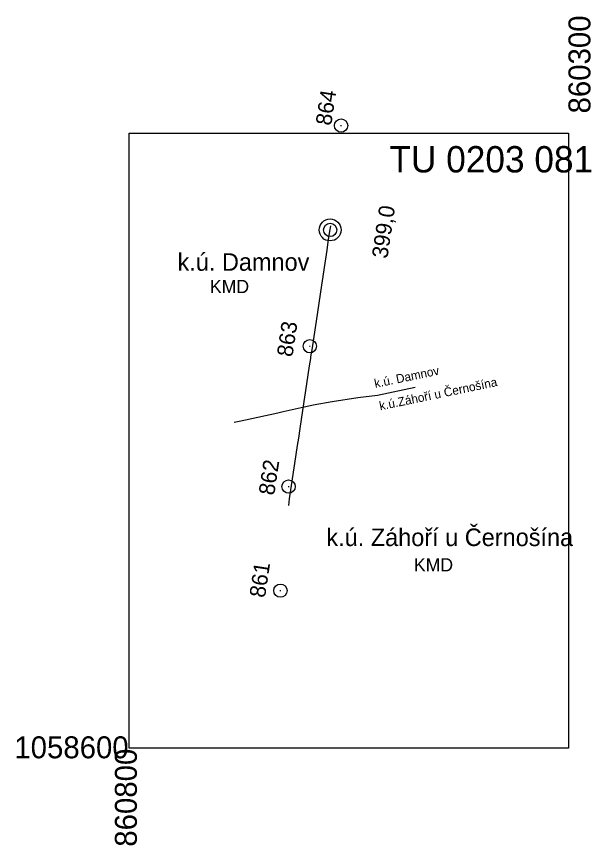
# Model space of a CAD drawing. Extents: x -867628 to -843257, y -1065611 to -1039859.
# Drawn here: x -860928 to -860274, y -1058711 to -1057767 of the extents above; entities that cross this region are included whole.
import ezdxf

# ---------------------------------------------------------------- set-up
doc = ezdxf.new("R2010")
doc.units = 0
for name, color, linetype in [('Vrstva 1', 7, 'Continuous'), ('Vrstva 10', 7, 'Continuous'), ('Vrstva 55', 7, 'Continuous'), ('Vrstva 62', 7, 'Continuous'), ('Vrstva 63', 7, 'Continuous'), ('Vrstva 7', 7, 'Continuous')]:
    doc.layers.add(name, color=color, linetype=linetype)

msp = doc.modelspace()

# ---------------------------------------------------------------- linework, layer by layer
at = {"layer": 'Vrstva 1'}
for points in [[(-860608.33, -1058255.64), (-860607.06, -1058247.12), (-860605.46, -1058236.48), (-860603.9, -1058226.17), (-860602.34, -1058215.79), (-860600.81, -1058205.62), (-860599.29, -1058195.55), (-860597.75, -1058185.28), (-860596.25, -1058175.34), (-860594.71, -1058165.1), (-860593.45, -1058156.76), (-860593.16, -1058154.84), (-860591.61, -1058144.56), (-860590.05, -1058134.21), (-860588.53, -1058124.15), (-860587, -1058113.98), (-860585.48, -1058103.9), (-860583.92, -1058093.51), (-860582.4, -1058083.4), (-860580.87, -1058073.24), (-860579.35, -1058063.13), (-860577.83, -1058053.08), (-860576.35, -1058043.25), (-860574.85, -1058033.29), (-860573.41, -1058023.69), (-860571.92, -1058013.85), (-860570.66, -1058005.49)], [(-860618.55, -1058323.98), (-860617.46, -1058316.3), (-860615.95, -1058306.1), (-860614.44, -1058296.09), (-860612.94, -1058286.12), (-860611.42, -1058276.06), (-860609.86, -1058265.76), (-860608.33, -1058255.64)]]:
    msp.add_lwpolyline(points, dxfattribs=at)
at = {"layer": 'Vrstva 55'}
for points in [[(-860568.88, -1058205.63), (-860539.83, -1058200.87), (-860517.57, -1058198.28), (-860474.56, -1058189.33)], [(-860680.68, -1058229.2), (-860673.04, -1058227.53), (-860667.77, -1058226.38), (-860630.98, -1058218.37), (-860624.65, -1058216.95), (-860604.45, -1058212.54), (-860599.07, -1058211.36), (-860590.56, -1058209.5), (-860568.88, -1058205.63)]]:
    msp.add_lwpolyline(points, dxfattribs=at)
at = {"layer": 'Vrstva 62'}
msp.add_lwpolyline([(-860300, -1057900), (-860300, -1058600), (-860800, -1058600), (-860800, -1057900)], close=True, dxfattribs=at)
at = {"layer": 'Vrstva 63'}
for p, q in [((-860559.4, -1057891.59), (-860558.4, -1057891.59)), ((-860595, -1058142.68), (-860594, -1058142.68)), ((-860619.14, -1058302.46), (-860618.14, -1058302.46)), ((-860628.49, -1058420.86), (-860627.49, -1058420.86))]:
    msp.add_line(p, q, dxfattribs=at)
for centre in [(-860558.9, -1057891.59), (-860594.5, -1058142.68), (-860618.64, -1058302.46), (-860627.99, -1058420.86)]:
    msp.add_circle(centre, 7.56, dxfattribs=at)
at = {"layer": 'Vrstva 7'}
for radius in [12.46, 7.52]:
    msp.add_circle((-860571.39, -1058010.29), radius, dxfattribs=at)

# ---------------------------------------------------------------- texts
at = {"layer": 'Vrstva 10'}
for p in [(-860708.18, -1058082.18), (-860475.94, -1058398.96)]:
    msp.add_text('KMD', height=15, dxfattribs=at).set_placement(p)
at = {"layer": 'Vrstva 55'}
for s, p in [('k.ú. Damnov', (-860745.1, -1058056.78)), ('k.ú. Záhoří u Černošína', (-860575.63, -1058370.11))]:
    msp.add_text(s, height=20, dxfattribs=at).set_placement(p)
for s, p in [('k.ú. Damnov', (-860519.98, -1058190.15)), ('k.ú.Záhoří u Černošína', (-860514.27, -1058215.69))]:
    msp.add_text(s, height=10, rotation=11.75499, dxfattribs=at).set_placement(p)
at = {"layer": 'Vrstva 62'}
for s, p in [('860300', (-860275, -1057877.72)), ('860800', (-860791.39, -1058712.26))]:
    msp.add_text(s, height=25, rotation=90, dxfattribs=at).set_placement(p)
for s, height, p in [('TU 0203 081', 30, (-860503.85, -1057944.88)), ('1058600', 25, (-860930.9, -1058611.65))]:
    msp.add_text(s, height=height, dxfattribs=at).set_placement(p)
at = {"layer": 'Vrstva 63'}
for s, rotation, p in [('864', 81.42563, (-860570.22, -1057892.21)), ('863', 81.43988, (-860614.37, -1058155.53)), ('862', 81.40232, (-860635.13, -1058313.01)), ('861', 81.42847, (-860645.59, -1058429.6))]:
    msp.add_text(s, height=18, rotation=rotation, dxfattribs=at).set_placement(p)
at = {"layer": 'Vrstva 7'}
msp.add_text('399,0', height=18, rotation=81.53143, dxfattribs=at).set_placement((-860506.19, -1058043.51))

doc.saveas('drawing.dxf')
